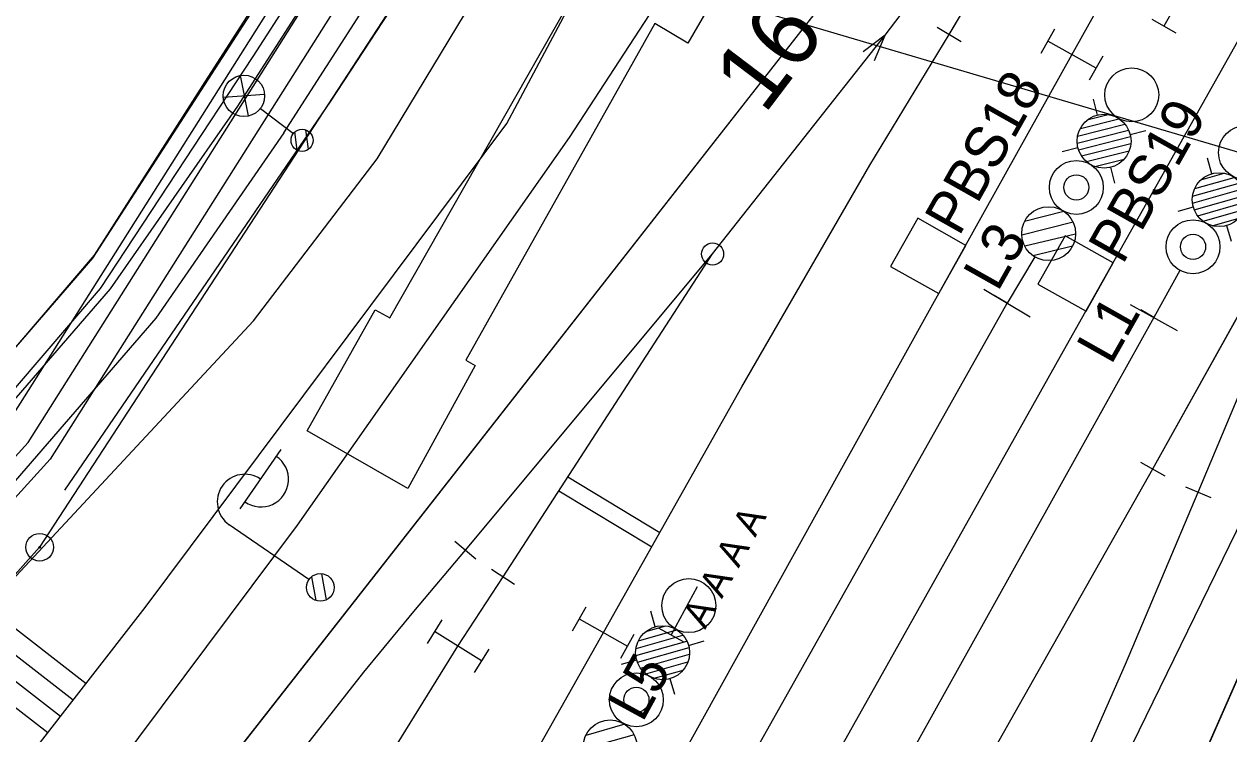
# Model space of a CAD drawing. Extents: x -781083 to -763634, y -1029516 to -1022695.
# Drawn here: x -765004.08 to -764960.51, y -1023855.35 to -1023829.68 of the extents above; entities that cross this region are included whole.
import ezdxf

# ---------------------------------------------------------------- set-up
doc = ezdxf.new("R2010")
doc.units = 0
for name, color, linetype in [('Default', 7, 'Continuous'), ('GasNet_ochr. pásmo', 7, 'Continuous'), ('GasNet_plyn STL', 7, 'Continuous'), ('Hranice parcel', 7, 'Continuous'), ('PS120111-MOK', 7, 'Continuous'), ('PS_12-01-10_Kabelizace_nove_kabelizace', 7, 'Continuous'), ('PS_12-01-11_SZZ_Slany_nove_prvky', 7, 'Continuous'), ('PS_12-01-11_SZZ_Slany_nove_prvky_popis', 7, 'Continuous'), ('PS_12-01-11_SZZ_Slany_rusene_prvky', 7, 'Continuous'), ('PS_12-01-11_SZZ_Slany_rusene_prvky_popis', 7, 'Continuous'), ('SO128401_EOV_trasa', 7, 'Continuous'), ('TS_veřejné vedení', 7, 'Continuous'), ('Vodafone_ vzduch', 7, 'Continuous'), ('Vrstva 1', 7, 'Continuous'), ('Vrstva 17', 7, 'Continuous'), ('Vrstva 2', 7, 'Continuous'), ('Vrstva 25', 7, 'Continuous'), ('Vrstva 3', 7, 'Continuous'), ('Vrstva 48', 7, 'Continuous'), ('Vrstva 49', 7, 'Continuous'), ('Vrstva 51', 7, 'Continuous'), ('Vrstva 7', 7, 'Continuous'), ('Značky bodu BP', 7, 'Continuous'), ('ČD Telematika_TK', 7, 'Continuous'), ('ČEZd_VN_podzemní', 7, 'Continuous')]:
    doc.layers.add(name, color=color, linetype=linetype)

# ---------------------------------------------------------------- blocks, each defined once
blk = doc.blocks.new('1.05')
at = {"layer": 'Značky bodu BP'}
for radius in [5, 0.303]:
    blk.add_circle((0, 0), radius, dxfattribs=at)
blk = doc.blocks.new('C669_1')
at = {"layer": 'Vrstva 25'}
for p, q in [((0, 5), (0, 40)), ((7, 40), (33, 40)), ((-4.78, -1.46), (1.44, 4.75)), ((-2.39, -4.37), (4.38, 2.4))]:
    blk.add_line(p, q, dxfattribs=at)
blk.add_circle((0, 0), 5, dxfattribs=at)
blk.add_circle((0, 0), 5, dxfattribs=at)
for centre, start, end in [((10, 40), 359.9999, 179.9999), ((20, 39.88), 179.2973, 0.7025)]:
    blk.add_arc(centre, 10, start, end, dxfattribs=at)
blk = doc.blocks.new('C187_9')
at = {"layer": 'Vrstva 25'}
for p, q in [((-4.94, 32.08), (4.99, 20.96)), ((-4.79, 20.77), (5.05, 31.98)), ((0, 19), (0.01, 4)), ((-3.9, -0.8), (0.81, 3.89)), ((-1.21, -3.77), (3.79, 1.23))]:
    blk.add_line(p, q, dxfattribs=at)
for centre, radius in [((-0.03, 26.48), 7.49), ((0, 0), 4), ((0, 0), 4)]:
    blk.add_circle(centre, radius, dxfattribs=at)
blk = doc.blocks.new('C084_2')
at = {"layer": 'Vrstva 2'}
blk.add_line((0, 5), (0, -5), dxfattribs=at)
blk = doc.blocks.new('C649_1')
at = {"layer": 'Vrstva 3'}
for p, q in [((-5, 10), (5, 10)), ((0, 10), (0, -10)), ((-5, -10), (5, -10))]:
    blk.add_line(p, q, dxfattribs=at)
blk = doc.blocks.new('C321')
at = {"layer": 'Vrstva 2'}
blk.add_lwpolyline([(9.66, 2.59), (0, 0), (9.66, -2.59)], dxfattribs=at)
blk = doc.blocks.new('C083_1')
at = {"layer": 'Vrstva 2'}
blk.add_circle((0, 0), 4, dxfattribs=at)
blk = doc.blocks.new('C529_1')
at = {"layer": 'Vrstva 2'}
for p, q in [((-2.45, 39.78), (-14.76, 27.47)), ((3.07, 39.65), (-11.57, 25)), ((7.2, 38.12), (-5.92, 25)), ((10.45, 35.71), (-0.26, 25)), ((12.93, 32.53), (5.4, 25)), ((14.55, 28.49), (11.05, 25)), ((0, 0), (0, 10))]:
    blk.add_line(p, q, dxfattribs=at)
blk.add_lwpolyline([(-15, 25), (15, 25)], dxfattribs=at)
blk.add_circle((0, 25), 15, dxfattribs=at)
blk.add_arc((0, 25), 15, 0, 180, dxfattribs=at)
blk = doc.blocks.new('POINT_DISPLAY')
at = {"layer": 'Default'}
blk.add_line((0, 0), (0, 0), dxfattribs=at)
blk = doc.blocks.new('C335')
at = {"layer": 'Vrstva 7'}
blk.add_blockref('POINT_DISPLAY', (0, 0), dxfattribs=at)
blk = doc.blocks.new('NS12')
at = {"layer": 'PS_12-01-11_SZZ_Slany_nove_prvky'}
for p, q in [((-10.61, 115.61), (-17, 122)), ((10.61, 115.61), (17, 122)), ((-14.95, 104.3), (0.71, 119.96)), ((-14.06, 99.88), (5.12, 119.06)), ((-13.82, 110.73), (-5.7, 118.86)), ((-12.24, 96.4), (8.61, 117.25)), ((-9.72, 93.62), (11.4, 114.74)), ((-6.52, 91.51), (13.48, 111.52)), ((-2.5, 90.23), (14.77, 107.5)), ((2.88, 90.31), (14.72, 102.15)), ((-10.61, 94.39), (-17, 88)), ((10.61, 94.39), (17, 88)), ((0.97, 59.97), (-14.97, 44.03)), ((8.42, 57.42), (-12.42, 36.58)), ((12.99, 52.49), (-7.8, 32.19)), ((14.97, 45.97), (-1, 30)), ((0, 30), (0, 0)), ((-15, 0), (15, 0))]:
    blk.add_line(p, q, dxfattribs=at)
for centre, radius in [((0, 135), 15), ((0, 105), 15), ((0, 75), 15), ((0, 75), 7), ((0, 45), 15)]:
    blk.add_circle(centre, radius, dxfattribs=at)
blk = doc.blocks.new('NS12_2')
at = {"layer": 'PS_12-01-11_SZZ_Slany_nove_prvky'}
for p, q in [((-10.61, 115.61), (-17, 122)), ((10.61, 115.61), (17, 122)), ((-14.95, 104.3), (0.71, 119.96)), ((-14.06, 99.88), (5.12, 119.06)), ((-13.82, 110.73), (-5.7, 118.86)), ((-12.24, 96.4), (8.61, 117.25)), ((-9.72, 93.62), (11.4, 114.74)), ((-6.52, 91.51), (13.48, 111.52)), ((-2.5, 90.23), (14.77, 107.5)), ((2.88, 90.31), (14.72, 102.15)), ((-10.61, 94.39), (-17, 88)), ((10.61, 94.39), (17, 88)), ((0.97, 59.97), (-14.97, 44.03)), ((8.42, 57.42), (-12.42, 36.58)), ((12.99, 52.49), (-7.8, 32.19)), ((14.97, 45.97), (-1, 30)), ((0, 30), (0, 0)), ((-15, 0), (15, 0))]:
    blk.add_line(p, q, dxfattribs=at)
for centre, radius in [((0, 135), 15), ((0, 105), 15), ((0, 75), 15), ((0, 75), 7), ((0, 45), 15)]:
    blk.add_circle(centre, radius, dxfattribs=at)
blk = doc.blocks.new('NS8')
at = {"layer": 'PS_12-01-11_SZZ_Slany_nove_prvky'}
for p, q in [((-10.61, 85.61), (-17, 92)), ((-14.92, 73.72), (1.27, 89.91)), ((-14.24, 79.71), (-4.75, 89.19)), ((-13.91, 69.42), (5.56, 88.89)), ((10.61, 85.61), (17, 92)), ((-11.99, 66.04), (8.96, 86.99)), ((-9.38, 63.35), (11.66, 84.39)), ((-6.1, 61.33), (13.69, 81.12)), ((-1.96, 60.16), (14.86, 76.98)), ((3.63, 60.45), (14.51, 71.33)), ((-10.61, 64.39), (-17, 58)), ((10.61, 64.39), (17, 58)), ((0, 30), (0, 0)), ((-15, 0), (15, 0))]:
    blk.add_line(p, q, dxfattribs=at)
for centre, radius in [((0, 105), 15), ((0, 75), 15), ((0, 45), 15), ((0, 45), 7)]:
    blk.add_circle(centre, radius, dxfattribs=at)
blk = doc.blocks.new('C016_4')
at = {"layer": 'PS_12-01-11_SZZ_Slany_rusene_prvky'}
for p, q in [((0, 5), (0, -5)), ((19.8, 0), (0, 0))]:
    blk.add_line(p, q, dxfattribs=at)
blk = doc.blocks.new('C649_1_1')
at = {"layer": 'PS_12-01-11_SZZ_Slany_rusene_prvky'}
for p, q in [((-5, 10), (5, 10)), ((0, 10), (0, -10)), ((-5, -10), (5, -10))]:
    blk.add_line(p, q, dxfattribs=at)
blk = doc.blocks.new('SB11_1')
at = {"layer": 'PS_12-01-11_SZZ_Slany_nove_prvky'}
blk.add_lwpolyline([(-125.2, 185.2), (-223.3, 10.9), (-49, -87.2), (49, 87.2)], close=True, dxfattribs=at)
blk = doc.blocks.new('SB11_2')
at = {"layer": 'PS_12-01-11_SZZ_Slany_nove_prvky'}
blk.add_lwpolyline([(-125, 185.3), (-223.2, 11), (-49.1, -87.1), (49.1, 87.1)], close=True, dxfattribs=at)
blk = doc.blocks.new('C016_14')
at = {"layer": 'PS_12-01-11_SZZ_Slany_rusene_prvky'}
for p, q in [((0, 5), (0, -5)), ((19.8, 0), (0, 0))]:
    blk.add_line(p, q, dxfattribs=at)

msp = doc.modelspace()

# ---------------------------------------------------------------- linework, layer by layer
at = {"layer": 'GasNet_ochr. pásmo'}
for points in [[(-765004.735, -1023844.204), (-764987.098, -1023816.295), (-764964.047, -1023784.681), (-764954.572, -1023774.882), (-764954.336, -1023774.638), (-764953.664, -1023774.538), (-764953.368, -1023774.703), (-764949.815, -1023776.676), (-764944.807, -1023779.62), (-764944.555, -1023779.767), (-764928.407, -1023789.665)], [(-764926.927, -1023792.918), (-764945.583, -1023781.483), (-764945.819, -1023781.344), (-764950.807, -1023778.412), (-764953.668, -1023776.824), (-764962.513, -1023785.971), (-764985.442, -1023817.419), (-765003.137, -1023845.42), (-765021.725, -1023865.911)]]:
    msp.add_lwpolyline(points, dxfattribs=at)
at = {"layer": 'GasNet_plyn STL'}
msp.add_lwpolyline([(-765056.262, -1023868.365), (-765056.064, -1023868.32), (-765055.22, -1023868.128), (-765047.384, -1023866.918), (-765047.344, -1023866.915), (-765022.199, -1023864.945), (-765003.936, -1023844.812), (-764986.27, -1023816.857), (-764963.28, -1023785.326), (-764953.853, -1023775.577), (-764950.311, -1023777.544), (-764945.313, -1023780.482), (-764945.069, -1023780.625), (-764927.667, -1023791.291)], dxfattribs=at)
at = {"layer": 'Hranice parcel'}
for points in [[(-764978.77, -1023810.6), (-765003.52, -1023848.6), (-765036.72, -1023885.86)], [(-765020.01, -1023859.43), (-765001.6, -1023838.14), (-764985.39, -1023813.06)], [(-764971.61, -1023815.75), (-764975.67, -1023822.76), (-764980.08, -1023830.37), (-764981.27, -1023829.66), (-764988.11, -1023841.84), (-764987.77, -1023842.03), (-764990.21, -1023846.47), (-764993.84, -1023844.39), (-764991.38, -1023840.01), (-764990.86, -1023840.3), (-764975.35, -1023813.06)]]:
    msp.add_lwpolyline(points, dxfattribs=at)
at = {"layer": 'PS120111-MOK'}
msp.add_lwpolyline([(-765225.805, -1024328.474), (-765227.041, -1024327.403), (-765189.607, -1024263.284), (-765167.089, -1024223.521), (-765111.836, -1024124.939), (-765108.851, -1024119.501), (-765085.73, -1024077.899), (-765081.023, -1024080.523), (-765060.822, -1024044.042), (-765057.835, -1024038.647), (-765021.888, -1023965.037), (-765009.529, -1023945.01), (-764990.029, -1023909.994), (-764973.93, -1023884.565), (-764957.796, -1023847.878), (-764953.349, -1023837.037), (-764952.504, -1023834.976), (-764951.393, -1023835.06)], dxfattribs=at)
at = {"layer": 'PS_12-01-10_Kabelizace_nove_kabelizace'}
for p, q in [((-765005.156, -1023867.179), (-764967.937, -1023819.655)), ((-764968.535, -1023839.77), (-764969.003, -1023839.49)), ((-764988.994, -1023876.176), (-764968.535, -1023839.77)), ((-764963.233, -1023840.29), (-764984.582, -1023878.634)), ((-764963.233, -1023840.29), (-764963.701, -1023840.01)), ((-764957.796, -1023847.878), (-764973.93, -1023884.565))]:
    msp.add_line(p, q, dxfattribs=at)
at = {"layer": 'SO128401_EOV_trasa'}
for points in [[(-764973.93, -1023884.565), (-765005.156, -1023867.179), (-764967.937, -1023819.655), (-764942.036, -1023784.592), (-764937.448, -1023776.793), (-764936.433, -1023777.403)], [(-765060.824, -1024044.045), (-765057.835, -1024038.647), (-765021.888, -1023965.037), (-765009.529, -1023945.01), (-764990.029, -1023909.994), (-764973.93, -1023884.565), (-764973.93, -1023884.565), (-764957.796, -1023847.878), (-764957.796, -1023847.878), (-764953.349, -1023837.037), (-764953.349, -1023837.037), (-764952.595, -1023837.444), (-764952.595, -1023837.444), (-764952.595, -1023837.444), (-764952.595, -1023837.444)]]:
    msp.add_lwpolyline(points, dxfattribs=at)
at = {"layer": 'TS_veřejné vedení'}
msp.add_lwpolyline([(-764962.654, -1023788.589), (-764977.401, -1023808.657), (-764993.006, -1023832.465), (-765002.622, -1023846.533)], dxfattribs=at)
at = {"layer": 'Vodafone_ vzduch'}
msp.add_line((-764902.64, -1023851.29), (-765047.77, -1023808.471), dxfattribs=at)
at = {"layer": 'Vrstva 1'}
for points in [[(-765011.125, -1023882.032), (-765006.787, -1023874.584), (-765003.188, -1023868.775), (-765000.244, -1023864.367), (-764995.829, -1023858.264), (-764991.795, -1023853.119), (-764989.992, -1023850.92), (-764988.125, -1023848.704), (-764979.186, -1023837.995), (-764972.943, -1023830.075), (-764972.169, -1023829.066), (-764962.145, -1023815.837), (-764953.22, -1023803.742), (-764952.283, -1023802.457), (-764942.467, -1023789.001), (-764933.609, -1023776.857), (-764932.714, -1023775.624), (-764932.358, -1023775.126), (-764928.839, -1023770.209), (-764926.844, -1023767.42), (-764917.098, -1023753.973), (-764910.61, -1023742.572)], [(-765057.199, -1024002.967), (-765051.483, -1023992.806), (-765043.706, -1023978.953), (-765034.751, -1023962.958), (-765025.899, -1023947.163), (-765016.568, -1023930.575), (-765007.818, -1023915.05), (-764998.815, -1023899.045), (-764993.349, -1023889.308), (-764987.511, -1023878.918), (-764981.006, -1023867.343), (-764973.154, -1023853.353), (-764966.496, -1023841.495), (-764959.274, -1023828.66), (-764951.948, -1023815.612), (-764946.772, -1023806.407), (-764938.618, -1023791.934), (-764931.244, -1023778.835), (-764930.485, -1023777.473), (-764927.033, -1023771.438), (-764925.317, -1023768.417), (-764917.098, -1023753.973)], [(-765061.157, -1024000.548), (-765054.406, -1023988.525), (-765046.25, -1023974.042), (-765038.306, -1023959.907), (-765029.522, -1023944.29), (-765019.951, -1023927.223), (-765010.85, -1023911.039), (-765002.788, -1023896.651), (-764999.751, -1023891.219), (-764995.793, -1023884.104), (-764991.163, -1023875.777), (-764986.062, -1023866.575), (-764981.011, -1023857.454), (-764976.168, -1023848.713), (-764971.336, -1023840.024), (-764966.193, -1023830.79), (-764963.989, -1023826.843), (-764958.821, -1023817.674), (-764953.901, -1023808.973), (-764950.727, -1023803.418), (-764942.467, -1023789.001)], [(-765021.966, -1023959.899), (-765020.98, -1023958.139), (-765020.338, -1023956.998), (-765016.5, -1023950.137), (-765007.832, -1023934.643), (-765003.16, -1023926.347), (-764995.027, -1023911.884), (-764988.083, -1023899.535), (-764983.024, -1023890.503), (-764978.046, -1023881.533), (-764973.443, -1023872.721), (-764971.379, -1023868.593), (-764967.7, -1023860.663), (-764964.253, -1023852.828), (-764961.628, -1023846.609), (-764955.193, -1023831.268), (-764949.378, -1023817.406), (-764948.769, -1023815.942), (-764946.974, -1023811.649), (-764945.113, -1023807.171), (-764938.618, -1023791.934)], [(-765066.823, -1024000.8), (-765059.521, -1023987.798), (-765051.083, -1023972.749), (-765042.307, -1023957.114), (-765034.527, -1023943.229), (-765024.842, -1023926.012), (-765014.604, -1023907.749), (-765007.197, -1023894.564), (-765001.299, -1023884.061), (-764995.865, -1023874.378), (-764990.286, -1023864.419), (-764985.503, -1023855.894), (-764983.132, -1023851.684), (-764978.128, -1023842.798), (-764973.494, -1023834.781), (-764970.63, -1023830.052), (-764962.145, -1023815.837)], [(-765052.709, -1024004.781), (-765046.025, -1023992.89), (-765034.924, -1023973.118), (-765026.269, -1023957.734), (-765017.76, -1023942.588), (-765010.012, -1023928.764), (-765001.938, -1023914.334), (-764994.407, -1023900.905), (-764986.605, -1023887.067), (-764981.397, -1023877.846), (-764975.574, -1023867.554), (-764972.605, -1023862.288), (-764968.241, -1023854.565), (-764963.27, -1023845.769), (-764955.193, -1023831.268)], [(-765076.991, -1024009.249), (-765068.63, -1023994.356), (-765060.962, -1023980.666), (-765051.422, -1023963.636), (-765043.392, -1023949.298), (-765036.095, -1023936.274), (-765028.081, -1023921.999), (-765021.192, -1023909.705), (-765014.101, -1023897.058), (-765011.259, -1023891.988), (-765007.442, -1023885.157), (-765001.636, -1023874.768), (-764998.254, -1023868.714), (-764992.689, -1023859.115), (-764988.392, -1023852.179), (-764986.762, -1023849.668), (-764979.186, -1023837.995)]]:
    msp.add_lwpolyline(points, dxfattribs=at)
at = {"layer": 'Vrstva 17'}
for points in [[(-764973.218, -1023793.881), (-764985.425, -1023812.874), (-764997.633, -1023831.896), (-765001.548, -1023838.038), (-765015.627, -1023854.487), (-765019.894, -1023858.999)], [(-764970.268, -1023812.149), (-764984.37, -1023833.783)], [(-764984.37, -1023833.783), (-764994.207, -1023847.799), (-765035.2, -1023902.657), (-765053.308, -1023935.706), (-765077.185, -1023979.953), (-765108.689, -1023993.473), (-765147.863, -1024026.342)]]:
    msp.add_lwpolyline(points, dxfattribs=at)
at = {"layer": 'Vrstva 2'}
for p, q in [((-764970.63, -1023830.052), (-764962.145, -1023815.837)), ((-764963.27, -1023845.769), (-764955.193, -1023831.268)), ((-764986.762, -1023849.668), (-764979.186, -1023837.995))]:
    msp.add_line(p, q, dxfattribs=at)
for points in [[(-764961.628, -1023846.609), (-764955.193, -1023831.268), (-764949.378, -1023817.406), (-764948.769, -1023815.942)], [(-764988.125, -1023848.704), (-764979.186, -1023837.995), (-764972.943, -1023830.075), (-764972.169, -1023829.066)]]:
    msp.add_lwpolyline(points, dxfattribs=at)
at = {"layer": 'Vrstva 48'}
for p, q in [((-765005.414, -1023850.75), (-765001.841, -1023853.528)), ((-765006.441, -1023851.852), (-765002.761, -1023854.712)), ((-765004.477, -1023852.428), (-765002.301, -1023854.12)), ((-765005.461, -1023853.563), (-765003.222, -1023855.304))]:
    msp.add_line(p, q, dxfattribs=at)
at = {"layer": 'Vrstva 49'}
for points in [[(-765026.593, -1023885.365), (-764999.705, -1023850.781), (-764986.63, -1023833.272), (-764978.594, -1023818.199), (-764974.02, -1023810.068), (-764969.31, -1023798.584)], [(-765029.569, -1023877.256), (-765024.382, -1023871.68), (-765019.041, -1023864.807), (-765012, -1023857.823), (-764995.786, -1023840.409), (-764991.309, -1023834.549), (-764976.248, -1023809.635)]]:
    msp.add_lwpolyline(points, dxfattribs=at)
at = {"layer": 'Vrstva 51'}
for points in [[(-764996.351, -1023832.643), (-764984.218, -1023813.742), (-764972.656, -1023795.959), (-764965.956, -1023786.782)], [(-764994.686, -1023833.618), (-764982.455, -1023814.573), (-764971.01, -1023797.036), (-764964.48, -1023788.003)], [(-765043.525, -1023860.782), (-765042.551, -1023874.682), (-765032.46, -1023870.68), (-765027.619, -1023868.41), (-765021.468, -1023862.596), (-765014.954, -1023855.423), (-765000.952, -1023839.251), (-764996.351, -1023832.643)], [(-764994.686, -1023833.618), (-764999.316, -1023840.313), (-765013.437, -1023856.631), (-765020.062, -1023863.988), (-765026.31, -1023869.822), (-765031.839, -1023872.542)]]:
    msp.add_lwpolyline(points, dxfattribs=at)
at = {"layer": 'Vrstva 7'}
for p, q in [((-764984.415, -1023846.051), (-764981.093, -1023848.062)), ((-764984.742, -1023846.555), (-764981.387, -1023848.585))]:
    msp.add_line(p, q, dxfattribs=at)
at = {"layer": 'ČD Telematika_TK'}
msp.add_lwpolyline([(-764972.556, -1023882.882), (-764969.78, -1023867.575), (-764954.962, -1023837.207), (-764946.646, -1023819.145), (-764922.208, -1023770.145), (-764907.866, -1023743.998)], dxfattribs=at)
at = {"layer": 'ČEZd_VN_podzemní'}
msp.add_lwpolyline([(-764917.991, -1023810.215), (-764918.562, -1023807.51), (-764919.66, -1023802.13), (-764920.94, -1023798.44), (-764932.4, -1023789.85), (-764941.94, -1023783.52), (-764953.83, -1023776.39), (-764957.16, -1023777.16), (-764959.07, -1023778.2), (-764961.32, -1023780.7), (-764970.6, -1023792.56), (-764976.55, -1023801.37), (-764982.69, -1023810.79), (-764988.88, -1023820.11), (-764995.81, -1023830.85), (-765001.33, -1023839.24), (-765010.71, -1023850.19)], dxfattribs=at)

# ---------------------------------------------------------------- block references
at = {"layer": 'PS_12-01-11_SZZ_Slany_nove_prvky', "xscale": 0.065}
for name, p, yscale, rotation in [('NS12', (-764968.535, -1023839.77), 0.065, -30.90847573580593), ('NS8', (-764963.233, -1023840.29), 0.06499999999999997, -29.07790106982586), ('NS12_2', (-764984.313, -1023858.377), 0.065, -29.116206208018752)]:
    msp.add_blockref(name, p, dxfattribs=dict(at, yscale=yscale, rotation=rotation))
at = {"layer": 'PS_12-01-11_SZZ_Slany_nove_prvky', "xscale": 0.010000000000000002, "yscale": 0.010000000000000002}
for name, p in [('SB11_2', (-764970.516, -1023838.553)), ('SB11_1', (-764965.186, -1023839.19))]:
    msp.add_blockref(name, p, dxfattribs=at)
at = {"layer": 'PS_12-01-11_SZZ_Slany_rusene_prvky'}
for name, p, xscale, yscale, rotation in [('C016_4', (-764962.863, -1023829.751), 0.1, 0.10000000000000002, 60.65434903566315), ('C649_1_1', (-764966.193, -1023830.79), 0.09999999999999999, 0.09999999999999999, -119.11620621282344), ('C016_14', (-764980.686, -1023851.768), 0.09999999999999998, 0.09999999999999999, 61.428315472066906), ('C649_1_1', (-764983.132, -1023851.684), 0.10000000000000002, 0.1, 60.612532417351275), ('C649_1_1', (-764988.392, -1023852.179), 0.10000000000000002, 0.1, -121.77909832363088)]:
    msp.add_blockref(name, p, dxfattribs=dict(at, xscale=xscale, yscale=yscale, rotation=rotation))
at = {"layer": 'Vrstva 2'}
for name, p, xscale, yscale, rotation in [('C529_1', (-764972.169, -1023829.066), 0.09999999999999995, 0.09999999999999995, 52.84766995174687), ('C084_2', (-764970.63, -1023830.052), 0.09999999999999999, 0.1, 59.1669759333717), ('C321', (-764972.943, -1023830.075), 0.09999999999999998, 0.09999999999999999, -127.49167392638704), ('C083_1', (-764979.186, -1023837.995), 0.1, 0.10000000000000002, 44.999999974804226), ('C084_2', (-764963.27, -1023845.769), 0.10000000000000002, 0.1, 60.88185747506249), ('C084_2', (-764961.628, -1023846.609), 0.1, 0.09999999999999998, 67.24304942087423), ('C084_2', (-764988.125, -1023848.704), 0.09999999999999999, 0.09999999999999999, 50.14879559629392), ('C084_2', (-764986.762, -1023849.668), 0.1, 0.09999999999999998, 57.016685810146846)]:
    msp.add_blockref(name, p, dxfattribs=dict(at, xscale=xscale, yscale=yscale, rotation=rotation))
at = {"layer": 'Vrstva 25', "xscale": 0.09999999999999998, "yscale": 0.09999999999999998}
for name, p, rotation in [('C187_9', (-764994.027, -1023833.883), 52.57090919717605), ('C669_1', (-764993.37, -1023850.054), 55.4227273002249)]:
    msp.add_blockref(name, p, dxfattribs=dict(at, rotation=rotation))
at = {"layer": 'Vrstva 3'}
for p, xscale, yscale, rotation in [((-764966.193, -1023830.79), 0.09999999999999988, 0.09999999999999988, -119.11620621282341), ((-764983.132, -1023851.684), 0.09999999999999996, 0.09999999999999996, 60.612532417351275), ((-764988.392, -1023852.179), 0.09999999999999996, 0.09999999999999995, -121.77909832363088)]:
    msp.add_blockref('C649_1', p, dxfattribs=dict(at, xscale=xscale, yscale=yscale, rotation=rotation))
at = {"layer": 'Vrstva 7', "xscale": 0.10000000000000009, "yscale": 0.10000000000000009, "rotation": 90}
msp.add_blockref('C335', (-764982.824, -1023847.365), dxfattribs=at)
at = {"layer": 'Značky bodu BP', "xscale": 0.1, "yscale": 0.10000000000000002}
msp.add_blockref('1.05', (-765003.52, -1023848.6), dxfattribs=at)

# ---------------------------------------------------------------- texts
at = {"layer": 'PS_12-01-11_SZZ_Slany_nove_prvky_popis'}
for s, rotation, p in [('PBS18', 60.6062, (-764970.273, -1023837.389)), ('PBS19', 60.6062, (-764964.356, -1023838.413)), ('L3', 60.6543, (-764968.876, -1023839.397)), ('L1', 60.565, (-764964.777, -1023842.044))]:
    msp.add_text(s, height=1.5, rotation=rotation, dxfattribs=at).set_placement(p)
at = {"layer": 'PS_12-01-11_SZZ_Slany_rusene_prvky'}
msp.add_text('  A A A A ', height=1, rotation=61.4283, dxfattribs=at).set_placement((-764979.808, -1023852.246))
at = {"layer": 'PS_12-01-11_SZZ_Slany_rusene_prvky_popis'}
msp.add_text('L5', height=1.5, rotation=61.4283, dxfattribs=at).set_placement((-764981.723, -1023854.975))
at = {"layer": 'Vrstva 2'}
msp.add_text('16', height=2.5, rotation=52.8477, dxfattribs=at).set_placement((-764977.313, -1023832.982))

doc.saveas('drawing.dxf')
